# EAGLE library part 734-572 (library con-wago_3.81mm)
Serie 734, Federleiste mit abgewinkelten Einlötstiften / Series 734, Female connector with angled solder pins Polzahl / Pole No.: 12 Bemessungsspannung / Rated Voltage: 160 V Nennstrom / Nominal Current: 10 A Lötstiftlänge: / Solder Pin Length: 3.8 mm Farbe / Color: orange / orange Stand: 01.01.2012. Die jeweils aktuellen Daten zu diesem Artikel finden Sie in unserem Produktkatalog, den Sie unter www.wago.com einsehen können. As of: 01/01/2012. Please find the newest data for this article in our product catalogue, which can be viewed under www.wago.com.
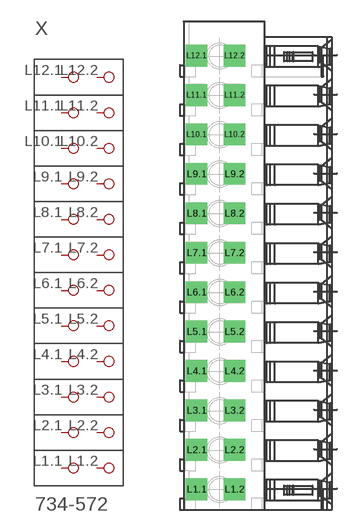
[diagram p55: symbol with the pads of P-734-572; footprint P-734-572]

Designator prefix X

## 734-572  [P-734-572]
L1.1  P1.1
L1.2  P1.2
L2.1  P2.1
L2.2  P2.2
L3.1  P3.1
L3.2  P3.2
L4.1  P4.1
L4.2  P4.2
L5.1  P5.1
L5.2  P5.2
L6.1  P6.1
L6.2  P6.2
L7.1  P7.1
L7.2  P7.2
L8.1  P8.1
L8.2  P8.2
L9.1  P9.1
L9.2  P9.2
L10.1  P10.1
L10.2  P10.2
L11.1  P11.1
L11.2  P11.2
L12.1  P12.1
L12.2  P12.2

## Footprint P-734-572 (pad centres in mm)
drill 1.4 square: L1.1 -5.979,-21.6; L1.2 -2.329,-21.6; L2.1 -5.979,-17.79; L2.2 -2.329,-17.79; L3.1 -5.979,-13.98; L3.2 -2.329,-13.98; L4.1 -5.979,-10.17; L4.2 -2.329,-10.17; L5.1 -5.979,-6.36; L5.2 -2.329,-6.36; L6.1 -5.979,-2.55; L6.2 -2.329,-2.55; L7.1 -5.979,1.26; L7.2 -2.329,1.26; L8.1 -5.979,5.07; L8.2 -2.329,5.07; L9.1 -5.979,8.88; L9.2 -2.329,8.88; L10.1 -5.979,12.69; L10.2 -2.329,12.69; L11.1 -5.979,16.5; L11.2 -2.329,16.5; L12.1 -5.979,20.31; L12.2 -2.329,20.31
